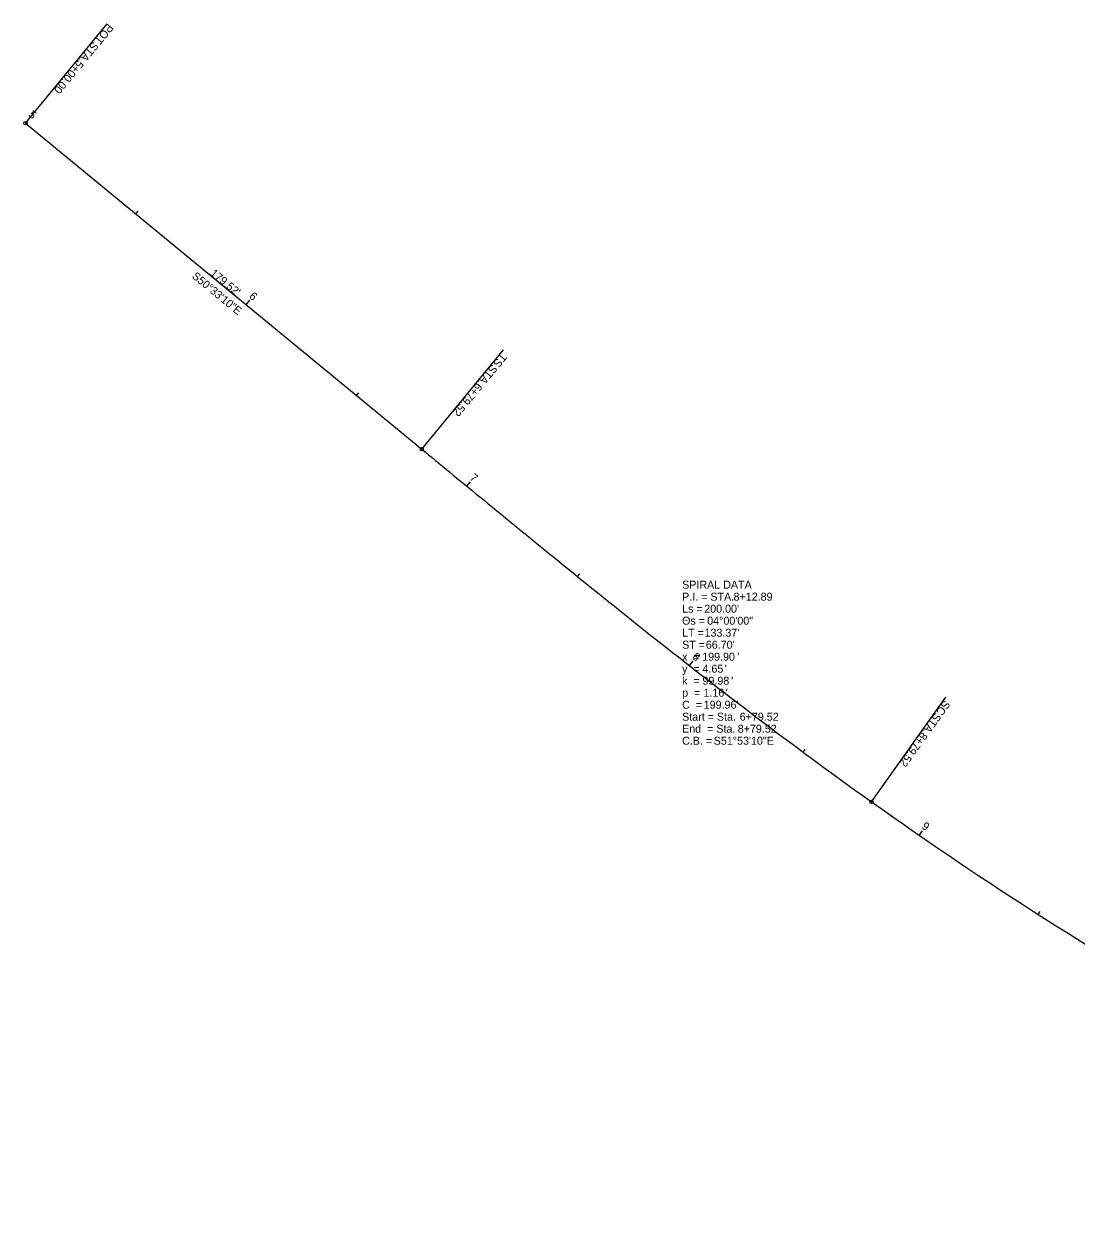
# Model space of a CAD drawing. Extents: x 2331955 to 2333190, y 280152 to 281038.
# Drawn here: x 2331955.3 to 2332323.6, y 280622 to 281038.2 of the extents above; entities that cross this region are included whole.
import ezdxf

# ---------------------------------------------------------------- set-up
doc = ezdxf.new("R2010")
doc.units = 0
for name, color, linetype in [('_CIVIL_CONSTRUCTION', 7, 'Continuous'), ('Default', 7, 'Continuous'), ('PF_X_Ground_Line', 7, 'Continuous'), ('RW_X_Esmt_SH', 7, 'Continuous'), ('RW_X_Esmt_SL', 7, 'Continuous'), ('RW_X_Fee_RW', 7, 'Continuous'), ('SV_X_Text', 7, 'Continuous')]:
    doc.layers.add(name, color=color, linetype=linetype)

msp = doc.modelspace()

# ---------------------------------------------------------------- linework, layer by layer
at = {"layer": '_CIVIL_CONSTRUCTION'}
msp.add_line((2331955.94, 281003.4), (2332094.57, 280889.33), dxfattribs=at)
msp.add_arc((2333082.61, 281932.82), 1432.39, 234.55278, 246.22798, dxfattribs=at)
msp.add_open_spline([(2332094.57, 280889.33), (2332101, 280884.04), (2332113.87, 280873.45), (2332139.66, 280852.33), (2332172.07, 280826.13), (2332204.93, 280800.51), (2332231.61, 280780.53), (2332245.1, 280770.75), (2332251.89, 280765.92)], degree=3, dxfattribs=at)
at = {"layer": 'Default'}
msp.add_line((2331955.94, 281003.4), (2332094.57, 280889.33), dxfattribs=at)
msp.add_arc((2333082.61, 281932.82), 1432.39, 234.55278, 246.22798, dxfattribs=at)
msp.add_open_spline([(2332094.57, 280889.33), (2332101, 280884.04), (2332113.87, 280873.45), (2332139.66, 280852.33), (2332172.07, 280826.13), (2332204.93, 280800.51), (2332231.61, 280780.53), (2332245.1, 280770.75), (2332251.89, 280765.92)], degree=3, dxfattribs=at)
at = {"layer": 'RW_X_Fee_RW'}
for p, q in [((2331955.94, 281003.4), (2331984.53, 281038.14)), ((2332094.57, 280889.33), (2332123.16, 280924.08)), ((2332251.89, 280765.92), (2332277.99, 280802.57))]:
    msp.add_line(p, q, dxfattribs=at)
for centre in [(2331955.94, 281003.4), (2332094.57, 280889.33), (2332251.89, 280765.92)]:
    msp.add_circle(centre, 0.6, dxfattribs=at)
at = {"layer": 'SV_X_Text'}
for p, q in [((2331955.94, 281003.4), (2331957.21, 281004.94)), ((2331994.55, 280971.63), (2331995.31, 280972.55)), ((2332033.16, 280939.86), (2332034.43, 280941.4)), ((2332071.77, 280908.09), (2332072.53, 280909.02)), ((2332110.39, 280876.33), (2332111.66, 280877.87)), ((2332149.12, 280844.71), (2332149.88, 280845.64)), ((2332188.24, 280813.58), (2332189.48, 280815.15)), ((2332228.01, 280783.27), (2332228.73, 280784.23)), ((2332268.66, 280754.16), (2332269.8, 280755.8)), ((2332310.29, 280726.47), (2332310.94, 280727.48))]:
    msp.add_line(p, q, dxfattribs=at)

# ---------------------------------------------------------------- texts
at = {"layer": 'PF_X_Ground_Line'}
msp.add_text("179.52'", height=2.8, rotation=320.5528, dxfattribs=at).set_placement((2332020.31, 280950.48))
at = {"layer": 'RW_X_Esmt_SH'}
for s, p in [('SPIRAL DATA', (2332185.67, 280840.49)), ('P.I. = STA. ', (2332185.67, 280836.29)), ('8+12.89', (2332203.66, 280836.29)), ('Ls = ', (2332185.67, 280832.09)), ("200.00'", (2332193.41, 280832.09)), ('Θs = ', (2332185.67, 280827.89)), ('04°00\'00"', (2332194.45, 280827.89)), ('LT = ', (2332185.67, 280823.69)), ("133.37'", (2332193.51, 280823.69)), ('ST = ', (2332185.67, 280819.49)), ("66.70'", (2332193.97, 280819.49)), ('199.90', (2332192.7, 280815.29)), ("'", (2332204.95, 280815.29)), ('x  = ', (2332185.67, 280815.29)), ('4.65', (2332192.8, 280811.09)), ("'", (2332200.58, 280811.09)), ('y  = ', (2332185.67, 280811.09)), ('k  = ', (2332185.67, 280806.89)), ('99.98', (2332192.8, 280806.89)), ("'", (2332202.82, 280806.89)), ('1.16', (2332193.15, 280802.69)), ("'", (2332200.93, 280802.69)), ('C  = ', (2332185.67, 280798.49)), ('p  = ', (2332185.67, 280802.69)), ("199.96'", (2332193.21, 280798.49)), ('Start = Sta. ', (2332185.67, 280794.29)), ('6+79.52', (2332205.81, 280794.29)), ('End  = Sta. ', (2332185.67, 280790.09)), ('8+79.52', (2332205.13, 280790.09)), ('C.B. = ', (2332185.67, 280785.89)), ('S51°53\'10"E', (2332196.73, 280785.89))]:
    msp.add_text(s, height=2.8, dxfattribs=at).set_placement(p)
at = {"layer": 'RW_X_Esmt_SL'}
msp.add_text('S50°33\'10"E', height=2.8, rotation=320.5528, dxfattribs=at).set_placement((2332013.94, 280949.46))
at = {"layer": 'RW_X_Fee_RW'}
for s, rotation, p in [('POT', 230.5528, (2331984.79, 281038.4)), (' STA. ', 230.5528, (2331980.26, 281032.9)), ('5+00.00', 230.5528, (2331974.34, 281025.7)), ('TS', 230.5528, (2332122.43, 280923.13)), (' STA. ', 230.5528, (2332119.81, 280919.96)), ('6+79.52', 230.5528, (2332113.89, 280912.76)), ('SC', 234.5528, (2332277.4, 280801.68)), (' STA. ', 234.5528, (2332274.87, 280798.13)), ('8+79.52', 234.5528, (2332269.46, 280790.53))]:
    msp.add_text(s, height=2.8, rotation=rotation, dxfattribs=at).set_placement(p)
at = {"layer": 'SV_X_Text'}
for s, rotation, p in [('5', 320.5528, (2331956.78, 281005.94)), ('6', 320.5528, (2332033.96, 280942.44)), ('7', 320.5947, (2332111.19, 280878.9)), ('8', 322.0043, (2332188.98, 280816.17)), ('9', 325.372, (2332269.26, 280756.78))]:
    msp.add_text(s, height=2.8, rotation=rotation, dxfattribs=at).set_placement(p)

doc.saveas('drawing.dxf')
